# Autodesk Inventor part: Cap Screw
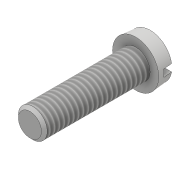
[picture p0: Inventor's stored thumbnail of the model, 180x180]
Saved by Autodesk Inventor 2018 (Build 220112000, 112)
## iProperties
Created: 2016-05
Part Number: Cap Screw
Material: Generic
Document SubType Name: Modeling
Designer: CADCIM
Density: 1 g/cm^3
Appearance: Default
Author: CADCIM
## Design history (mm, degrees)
sketch "Sketch2"
  geometry: C1 r 4.8 at (0, 0); 1 further point
  constraints: 1 centre point, 1 coincident
  dimensions: "d0" = 9.6 diameter of C1
extrude "Extrusion1" new body sketch "Sketch2" distance "d1" = 3; taper "d2" = -5 deg
sketch "Sketch3"
  geometry: C1 r 3 at (0, 0); 1 further point
  constraints: 1 centre point, 1 coincident
  dimensions: "d3" = 6 diameter of C1
extrude "Extrusion2" join sketch "Sketch3" distance "d4" = 22; taper "d5" = 0 deg
sketch "Sketch4"
  geometry: L1 (-13.358, -0.75)-(13.048, -0.75); L2 (13.048, -0.75)-(13.048, 0.75); L3 (13.048, 0.75)-(-13.358, 0.75); L4 (-13.358, 0.75)-(-13.358, -0.75); L5 (0, 0)-(-15.613, 0)
  constraints: 10 end point, 3 parallel, 1 horizontal, 1 perpendicular, 1 other
  dimensions: "d6" = 1.5 distance of L3.end L1.start
extrude "Extrusion3" cut sketch "Sketch4" distance "d7" = 1.8; taper "d8" = 0 deg
thread "Thread1" dims "d9" = 10, "d10" = 0
chamfer "Chamfer1" distance "d11" = 0.6; stored, may be unused: second distance "d12" = 2, angle "d13" = 45 deg
body "Solid1"
